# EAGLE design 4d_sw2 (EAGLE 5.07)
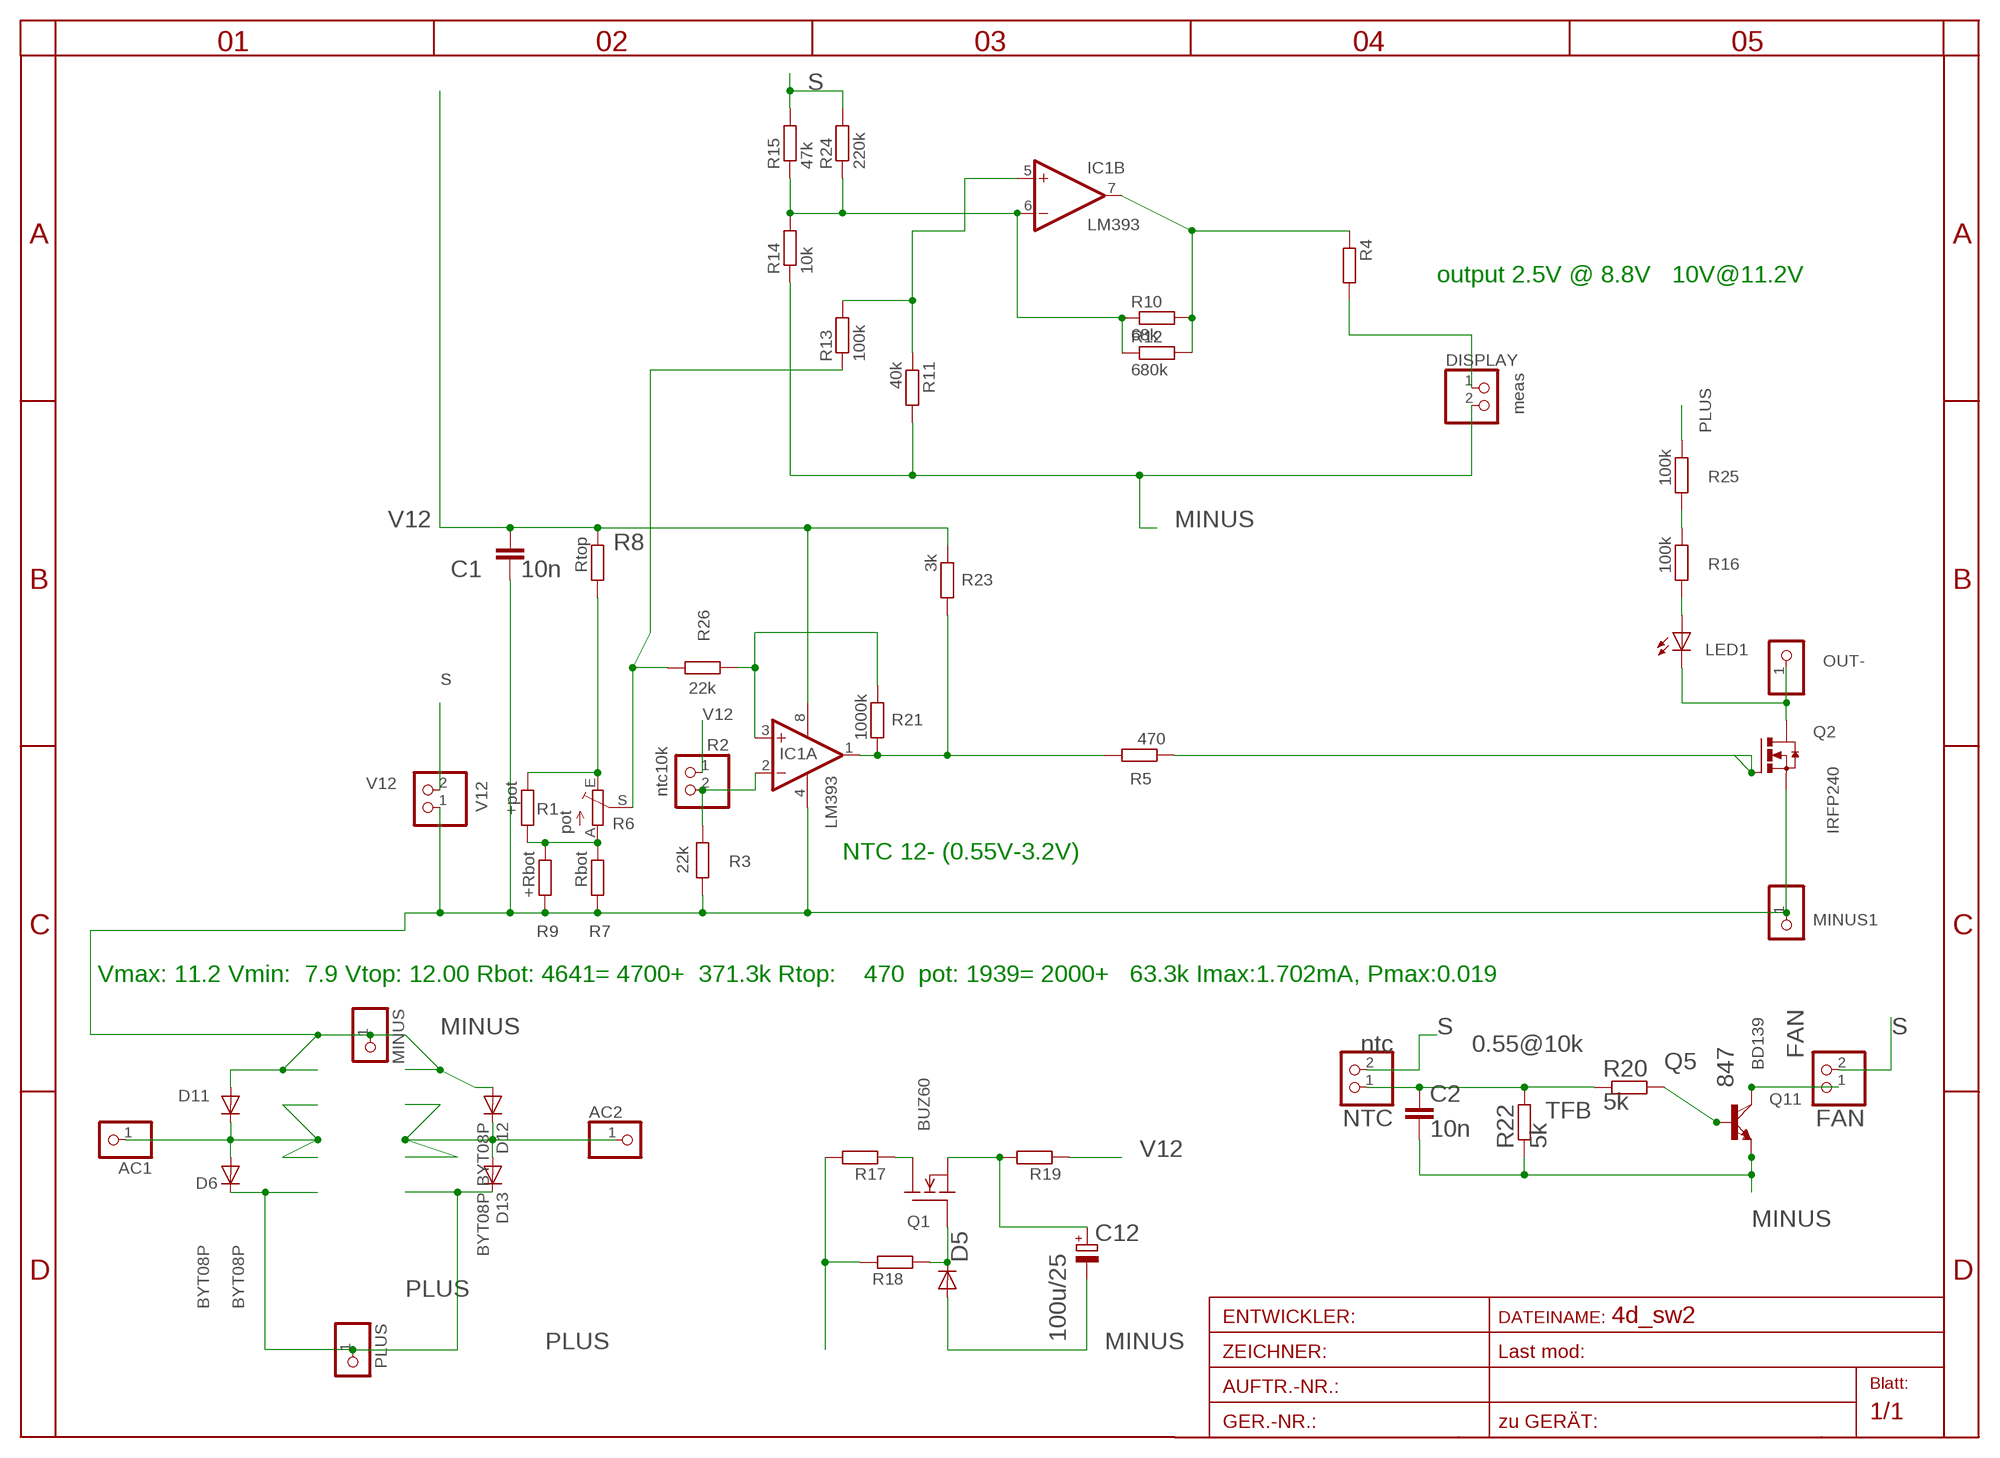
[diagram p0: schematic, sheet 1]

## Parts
AC1  PINHD-1X12MM2  [1X2MM2]
AC2  PINHD-1X12MM2  [1X2MM2]
C1  10n  C-EUC0805  [C0805]
C2  10n  C-EUC0805  [C0805]
C12  100u/25  CPOL-EUD  [PANASONIC_D]
D5  DIODE-MINIMELF  [MINIMELF]
D6  BYT08P  [TO220ACS]
D11  BYT08P  [TO220ACS]
D12  BYT08P  [TO220ACS]
D13  BYT08P  [TO220ACS]
DISPLAY  meas  PINHD-1X2STR  [1X02]
FAN  FAN  PINHD-1X2STR  [1X02]
IC1  LM393  LM358D  [SO08]
LED1  LEDSMT1206  [1206]
MINUS  PINHD-1X12MM2  [1X2MM2]
MINUS1  PINHD-1X12MM2  [1X2MM2]
NTC  ntc  PINHD-1X2STR  [1X02]
OUT-  PINHD-1X12MM2  [1X2MM2]
PLUS  PINHD-1X12MM2  [1X2MM2]
Q1  BUZ60  [TO220]
Q2  IRFP240  [TO247BV]
Q5  847  BC847SMD  [SOT23]
Q11  BD139  [TO126AV]
R1  +pot  R-EU_R0805  [R0805]
R2  ntc10k  PINHD-1X2STR  [1X02]
R3  22k  R-EU_R1206  [R1206]
R4  R-EU_R0805  [R0805]
R5  470  R-EU_0207/20  [0207/20]
R6  pot  TRIM_EU-RAND160  [RANDL]
R7  Rbot  R-EU_R0805  [R0805]
R8  Rtop  R-EU_R1206  [R1206]
R9  +Rbot  R-EU_R0805  [R0805]
R10  68k  R-EU_R0805  [R0805]
R11  40k  R-EU_R0805  [R0805]
R12  680k  R-EU_R0805  [R0805]
R13  100k  R-EU_0207/10  [0207/10]
R14  10k  R-EU_R0805  [R0805]
R15  47k  R-EU_R0805  [R0805]
R16  100k  R-EU_R1206  [R1206]
R17  R-EU_0207/10  [0207/10]
R18  R-EU_0207/15  [0207/15]
R19  R-EU_0204/7  [0204/7]
R20  5k  R-EU_R0805  [R0805]
R21  1000k  R-EU_R1206  [R1206]
R22  5k  R-EU_R0805  [R0805]
R23  3k  R-EU_R0805  [R0805]
R24  220k  R-EU_R0805  [R0805]
R25  100k  R-EU_0207/22  [0207/22]
R26  22k  R-EU_R0805  [R0805]
V12  V12  PINHD-1X2STR  [1X02]

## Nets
A: R1.2 R6.A R7.1 R9.1
AC1: AC1.1 D6.A D11.C
AC2: AC2.1 D12.C D13.A
E: R1.1 R6.E R8.2
MINUS: C1.2 C2.2 C12.- D5.A D11.A D12.A DISPLAY.2 IC1.4(P:V-) MINUS1.1 MINUS.1 Q2.S Q5.2(E) Q11.E R3.2 R7.2 R9.2 R11.2 R14.1 R22.1 V12.1
N$1: DISPLAY.1 R4.2
N$2: R16.1 R25.2
N$4: IC1.3(A:+IN) R21.1 R26.2
N$5: IC1.2(A:-IN) R2.2 R3.1
N$6: Q2.G R5.1
N$7: FAN.1 Q5.3(C) Q11.C
N$8: LED1.C OUT-.1 Q2.D
N$9: R6.S R13.1 R26.1
N$10: Q1.2(D) R17.1
N$11: IC1.7(B:OUT) R4.1 R10.2 R12.2
N$12: D5.C Q1.1(G) R18.1
N$13: Q5.1(B) Q11.B R20.2
N$14: LED1.A R16.2
PLUS: D6.C D13.C PLUS.1 R17.2 R18.2 R25.1
S: C12.+ FAN.2 NTC.2 Q1.3(S) R15.2 R19.2 R24.2 V12.2
TFB: C2.1 NTC.1 R20.1 R22.2
V12: C1.1 IC1.8(P:V+) R2.1 R8.1 R19.1 R23.1
V-: IC1.6(B:-IN) R10.1 R12.1 R14.2 R15.1 R24.1
V]: IC1.5(B:+IN) R11.1 R13.2
VOUT1: IC1.1(A:OUT) R5.2 R21.2 R23.2

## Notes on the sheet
- output 2.5V @ 8.8V   10V@11.2V
- NTC 12- (0.55V-3.2V)
- Vmax: 11.2 Vmin:  7.9 Vtop: 12.00 Rbot: 4641= 4700+  371.3k Rtop:    470  pot: 1939= 2000+   63.3k Imax:1.702mA, Pmax:0.019
- 0.55@10k

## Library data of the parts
AC1 AC2 MINUS MINUS1 OUT- PLUS = pinhead:PINHD-1X1: PIN HEADER
C1 C2 = rcl:C-EU: CAPACITOR, European symbol
C12 = rcl:CPOL-EU: POLARIZED CAPACITOR, European symbol
D5 = diode:DIODE-: DIODE
D6 D11-D13 = diode:BYT08P: DIODE
DISPLAY FAN NTC R2 V12 = pinhead:PINHD-1X2: PIN HEADER
IC1 = linear:LM358: OP AMP also LM158; LM258; LM2904 Source: http://cache.national.com/ds/LM/LM158.pdf
LED1 = led:LED: LED
Q1 = transistor-fet(2):BUZ60: N-Channel Enhancement MOSFET 400V; 5,5A; 1,0Ohm
Q2 = transistor-power:IRFP240: HEXFET Power MosFet Source: http://www.irf.com/
Q5 = transistor-npn:BC847*: NPN Transistor
Q11 = transistor-power:BD139: NPN TRANSISTOR
R1 R3 R4 R7-R12 R14-R24 R26 = rcl:R-EU_: RESISTOR, European symbol
R5 R13 R25 = rcl-2:R-EU_: RESISTOR, European symbol
R6 = pot:TRIM_EU-: POTENTIOMETER

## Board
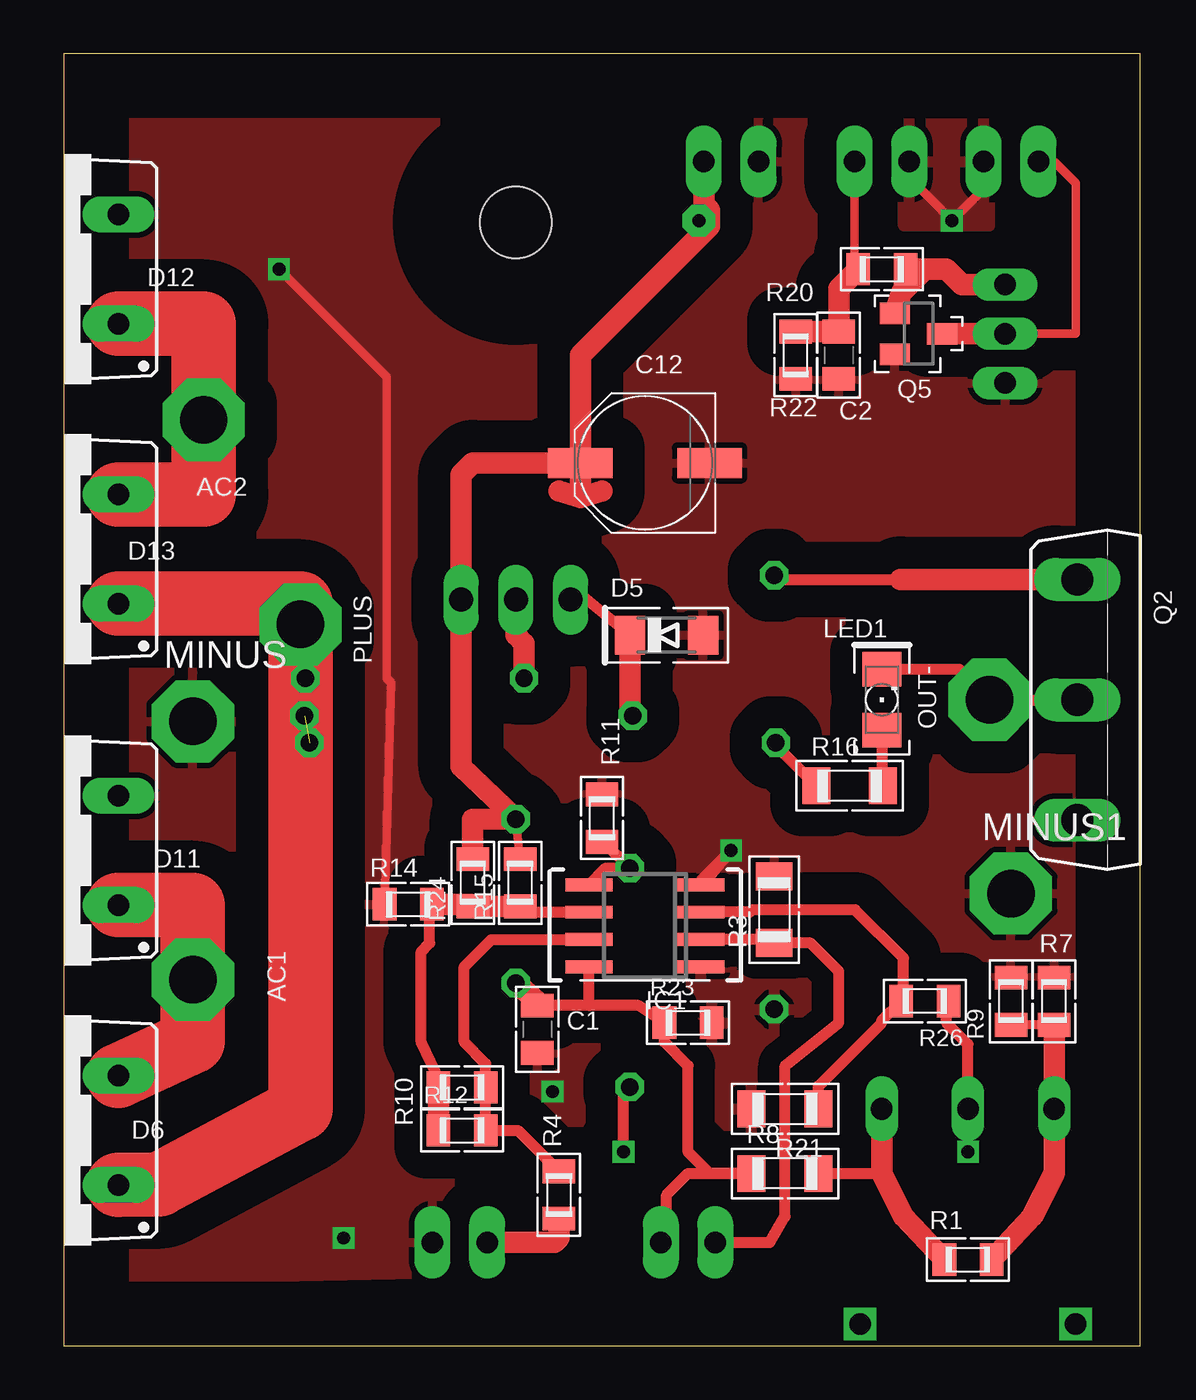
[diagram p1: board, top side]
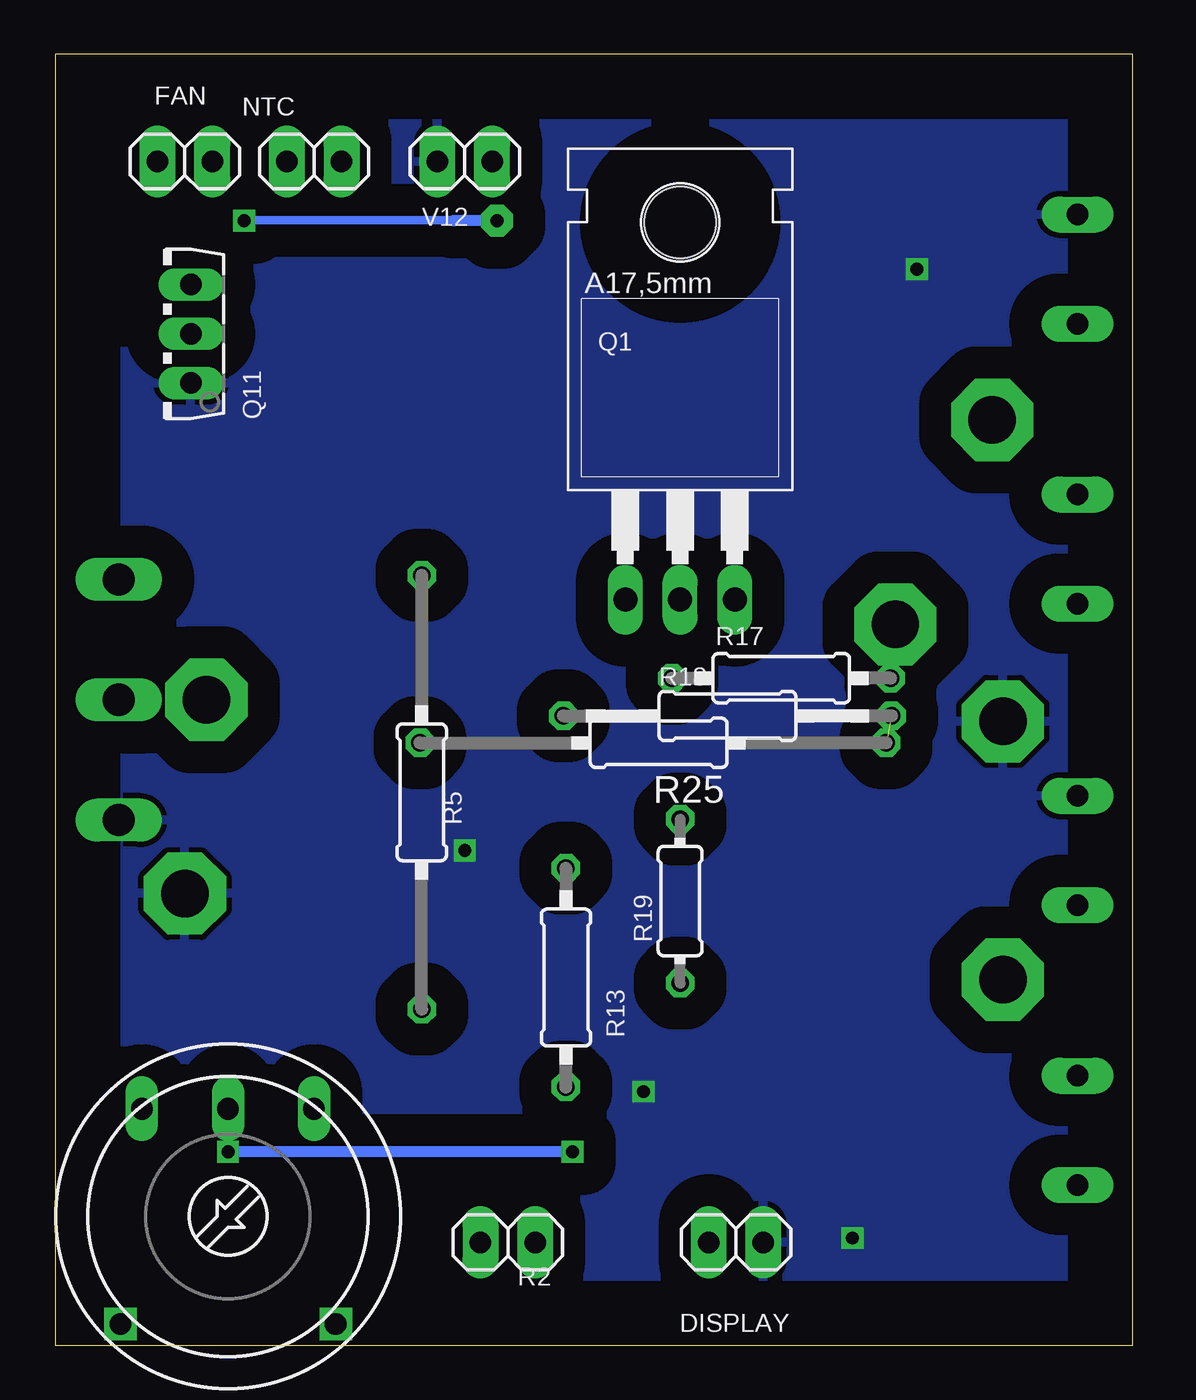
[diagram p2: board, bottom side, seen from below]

Size 50 x 60 mm. Coordinates in mm from the lower left corner, seen from the top.
Outline: 0,0 50,0 50,60 0,60 0,0
Copper layers (1*16): Top 0.035mm / dielectric 1.5mm / Bottom 0.035mm
Design rules "default *": minimum track width 10mil, minimum drill 20mil, track to track 8mil, track to pad 8mil, pad to pad 8mil, via to via 8mil, smd to smd 8mil, copper to edge 3mm, drill to drill 8mil, minimum pad ring 10mil, minimum via ring 8mil, stop-mask expansion 4mil, vias tented up to drill 0mil, thermal gap 10mil

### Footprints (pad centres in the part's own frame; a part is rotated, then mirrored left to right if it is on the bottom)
1X2MM2 = drill 2.2 pad 3.81 octagon: 1 0,0
C0805 = smd 1.1 x 1.5: 1 -1.1,0; 2 1.1,0
PANASONIC_D = smd 3 x 1.4: + 3,0; - -3,0
MINIMELF = smd 1.4 x 1.8: A 1.7,0; C -1.7,0
TO220ACS = drill 1 pad 1.676 long: A 2.54,-2.54; C -2.54,-2.54
1X02 = drill 1 pad 1.676 long: 1 -1.27,0; 2 1.27,0
SO08 = smd 0.6 x 2.2: 1 -1.905,-2.6; 2 -0.635,-2.6; 3 0.635,-2.6; 4 1.905,-2.6; 5 1.905,2.6; 6 0.635,2.6; 7 -0.635,2.6; 8 -1.905,2.6
1206 = smd 1.6 x 1.803: A -1.422,0; C 1.422,0
TO220 = drill 1.118 long: 1 -2.54,-6.35; 2 0,-6.35; 3 2.54,-6.35 | hole 3.302: 0,11.176
TO247BV = drill 1.499 long: D 0,-2.921; G -5.588,-2.921; S 5.588,-2.921
SOT23 = smd 1 x 1.4: 1 -0.95,-1.1; 2 0.95,-1.1; 3 0,1.1
TO126AV = drill 1 pad 1.27 long: B 2.286,-1.27; C 0,-1.27; E -2.286,-1.27
R0805 = smd 1.1 x 1.5: 1 -1.1,0; 2 1.1,0
R1206 = smd 1.3 x 1.7: 1 -1.55,0; 2 1.55,0
0207/20 = drill 0.813 octagon: 1 -10.08,0; 2 10.08,0
RANDL = drill 1 long: A -4,5; E 4,5; S 0,5 | drill 1 square: P$1 -5,-5; P$2 5,-5
0207/10 = drill 0.813 octagon: 1 -5.08,0; 2 5.08,0
0207/10' = drill 0.8 octagon: 1 -5.08,0; 2 5.08,0
0207/15 = drill 0.813 octagon: 1 -7.62,0; 2 7.62,0
0204/7 = drill 0.813 octagon: 1 -3.81,0; 2 3.81,0
0207/22 = drill 0.813 octagon: 1 -10.58,0; 2 11.08,0

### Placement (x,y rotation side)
AC1  6,17 270 top
AC2  6.5,43 0 top
C1  22,14.7 270 top
C2  36,46 270 top
C12  27,41 180 top
D5  28,33 0 top
D6  0,10 90 top
D11  0,23 90 top
D12  0,50 90 top
D13  0,37 90 top
DISPLAY  18.4,4.8 0 bottom
FAN  44,55 0 bottom
IC1  27,19.5 90 top
LED1  38,30 90 top
MINUS  6,29 0 top
MINUS1  44,21 0 top
NTC  38,55 180 bottom
OUT-  43,30 90 top
PLUS  11,33.5 270 top
Q1  21,41 0 bottom
Q2  50,30 270 top
Q5  39.7,47 270 top
Q11  45,47 90 bottom
R1  42,4 0 top
R2  29,4.8 180 bottom
R3  33,20.25 90 top
R4  23,7 270 top
R5  33,25.7 270 bottom
R6  42,6 0 bottom
R7  46,16 90 top
R8  33.5,8 0 top
R9  44,16 90 top
R10  18.5,12 0 top
R11  25,24.5 90 top
R12  18.5,10 0 top
R13  26.3,17.1 90 bottom
R14  16,20.5 0 top
R15  21.2,21.5 90 top
R16  36.5,26 0 top
R17  [0207/10']  16.3,31 0 bottom
R18  18.8,29.25 0 bottom
R19  21,20.65 90 bottom
R20  38,50 0 top
R21  33.5,11 180 top
R22  34,46 90 top
R23  29,15 0 top
R24  19,21.5 90 top
R25  22,28 180 bottom
R26  40,16 180 top
V12  31,55 0 bottom

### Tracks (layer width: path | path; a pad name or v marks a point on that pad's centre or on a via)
A
  Top 0.406: R7.1 R9.1
  Top 1: R1.2 45,6 46,8 R6.A R7.1
AC1
  Top 3: D6.A 6,14.14 AC1.1 6,20.46 D11.C
AC2
  Top 3: D12.C 6.5,47.46 AC2.1 6.5,39.54 D13.A
E
  Top 0.5: R8.2 38,8
  Top 1: R6.E 38,8 39,6 R1.1
MINUS  (via drill 0.6)
  Top 0.4: R14.1 15.2,30.8 15,31 15,45 v10,50
  Top 0.5: IC1.4 29.6,21.6 v31,23 30,21.8 IC1.4
  other vias: 22.7,11.8 13,5
  pour Bottom (isolate 1.5): 15,59 48,59 48,3 0,2 -1,57
  pour Top (isolate 1.5, rank 4): 17,60 50,60 50,4 2,3 1,58
N$1
  Top 1: DISPLAY.1 22.8,4.8 23,5 R4.2
N$2
  Top 0.5: R25.2 33.08,27.87 R16.1
N$4
  Top 0.5: IC1.3 31.86,20.14 32,20.25 36.75,20.25 39,18 39,16.1 R26.2 38,15.1 38,15 35.05,12.05 R21.1
N$5
  Top 0.5: R2.2 32.8,4.8 33.5,6 33.5,13 36,15 36,17.39 34.69,18.7 R3.1 32.52,18.86 IC1.2
N$6
  Top 0.5: 38.86,35.59 33.19,35.59 R5.1
  Top 1: 38.86,35.59 Q2.G
N$7
  Top 0.4: FAN.1 46,55 47,54 47,47 Q11.C
  Top 1: Q5.3 Q11.C
N$8
  Top 0.5: Q2.D OUT-.1 41.58,31.42 LED1.C
N$9  (via drill 0.6)
  Top 0.5: v42,9 R6.S 42,14 41,15 41,15.9 R26.1 | v26,9 26,11.72 R13.1
  Bottom 0.5: v26,9 v42,9
N$10
  Top 1: R17.1 21.38,32.62 21,33 Q1.2
N$11
  Top 0.5: IC1.7 19.86,18.86 18.6,17.6 18.6,14.1 19.6,13.1 R10.2 R12.2 21.1,10 R4.1
N$12
  Top 0.5: D5.C 23.89,35 Q1.1
  Top 1: D5.C 26.3,29.37 R18.1
N$13
  Top 1: Q11.B 41.71,49.29 41,50 40,50 | 40,50 R20.2 | Q5.1 38.9,48.9 40,50
N$14
  Top 0.5: R16.2 LED1.A
PLUS  (1 unrouted)
  Top 0.5: R18.2 11.15,30.93 R17.2 11.22,32.78 11,33
  Top 3: D6.C 4.44,7.5 11,11 11,33 PLUS.1 11,34.46 D13.C
S  (via drill 0.6, 0.6 pad 1.5)
  Top 0.4: R15.2 20.96,24.7 R19.2 | NTC.2 39.27,54.27 v41.25,52.25 42.73,53.73 FAN.2
  Top 1: 29.73,53 29.73,52.52 v29.5,52.25 | 29.73,53 V12.2 | C12.+ 24,46 30,52 30,52.73 29.73,53 | C12.+ 19,41 18.46,40.46 Q1.3 18.46,26.9 R19.2 19,24.43 R24.2 | 24,39.4 23,39.7 | 24,39.4 25,39.7 | C12.+ 24,39.4
  Bottom 0.406: 31.54,52.27 v41.25,52.25
  Bottom 0.5: v29.5,52.25 31.52,52.25 31.54,52.27
  pour Top (isolate 1): 39,55 39,57 43,57 43,52 39,52
TFB
  Top 0.4: NTC.1 36.73,50.17 R20.1
  Top 1: R22.2 C2.1 36,49.1 R20.1
V12
  Top 0.5: 24.4,15.8 IC1.8 | 24.4,15.8 C1.1 | R2.1 28,5.07 28,7 29,8 R8.1 30,8 29,9 29,13 27.9,14.1 R23.1 26.7,15.8 24.4,15.8
  Top 1: C1.1 22.2,15.8 R19.1
V-
  Top 0.5: IC1.6 21.46,20.14 R15.1 | R10.1 17.5,12.2 16.6,14.1 16.6,18.3 17,18.7 17,20.4 R14.2
  Top 1: R12.1 R10.1 | R14.2 18.9,20.5 R24.1 R15.1
V]
  Top 0.5: R11.1 25.08,23.4 R13.2 25.18,22.18 IC1.5
VOUT1
  pour Top (isolate 1): 29,17 30,18 34,18 35,17 35,15 34,14 34,11 33,10 31,10 30,11 30,15 29,16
